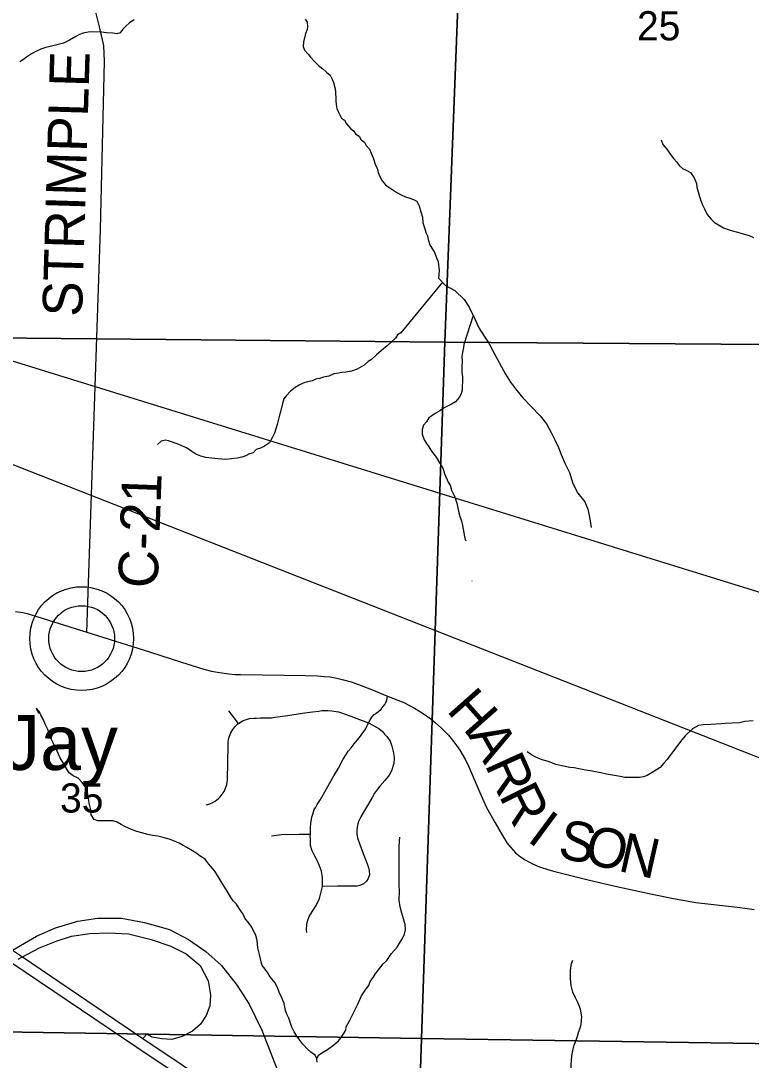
# Model space of a CAD drawing. Extents: x -7.5 to 26.5, y 3.5 to 25.5.
# Drawn here: x -0.916 to 0.131, y 19.097 to 20.587 of the extents above; entities that cross this region are included whole.
import ezdxf

# ---------------------------------------------------------------- set-up
doc = ezdxf.new("R2010")
doc.units = 0
for name, color, linetype in [('GM_X_Corporation', 7, 'Continuous'), ('GM_X_County_Road', 7, 'Continuous'), ('GM_X_County_Road_Text', 7, 'Continuous'), ('GM_X_Interchange_Ramps', 7, 'Continuous'), ('GM_X_Interstate_Route', 7, 'Continuous'), ('GM_X_Minor_River', 7, 'Continuous'), ('GM_X_Section_Text', 7, 'Continuous'), ('GM_X_Township_Road', 7, 'Continuous'), ('GM_X_Unincorporated', 7, 'Continuous'), ('GM_X_Unincorporated_Location', 7, 'Continuous'), ('GM_X_Unincorporated_Text', 7, 'Continuous'), ('GM_X_US_Route', 7, 'Continuous'), ('SH_Text', 7, 'Continuous')]:
    doc.layers.add(name, color=color, linetype=linetype)

msp = doc.modelspace()

# ---------------------------------------------------------------- linework, layer by layer
at = {"layer": 'GM_X_Corporation'}
for points in [[(-1.2798, 21.1309), (-1.0307, 21.1237), (-0.2705, 21.1018), (-0.3082, 20.1265), (-1.3089, 20.136)], [(-1.3089, 20.136), (-0.3082, 20.1265), (-0.3419, 19.1283), (-1.3364, 19.1437)], [(-0.3082, 20.1265), (0.6831, 20.1191), (0.6477, 19.1133), (-0.3419, 19.1283)], [(-0.3419, 19.1283), (-0.3746, 18.1372), (-1.2757, 18.1481), (-1.2769, 18.1576), (-1.2831, 18.1672), (-1.2995, 18.1782), (-1.3164, 18.1862), (-1.3281, 18.1892), (-1.3372, 18.1894), (-1.3579, 18.1948), (-1.3364, 19.1437)], [(0.6477, 19.1133), (0.6301, 18.1235), (-0.3746, 18.1372), (-0.3419, 19.1283)]]:
    msp.add_lwpolyline(points, close=True, dxfattribs=at)
msp.add_lwpolyline([(0.6831, 20.1191), (-0.3082, 20.1265), (-0.2705, 21.1018), (0.8624, 21.0618)], dxfattribs=at)
at = {"layer": 'GM_X_County_Road'}
for points in [[(-0.8217, 19.7108), (-0.8019, 20.2879), (-0.7964, 20.5294), (-0.7974, 20.5511), (-0.8024, 20.5748), (-0.8093, 20.6016), (-0.8189, 20.625), (-0.8374, 20.657), (-0.8664, 20.6927), (-0.8711, 20.6997), (-0.8729, 20.7047), (-0.872, 20.7107), (-0.7645, 20.9229), (-0.7533, 20.9424), (-0.7372, 20.9628), (-0.7249, 20.9811), (-0.717, 20.9931), (-0.7065, 21.016), (-0.689, 21.0677)], [(-0.9239, 19.7405), (-0.9133, 19.7386), (-0.9072, 19.7372), (-0.8936, 19.7333), (-0.8217, 19.7108), (-0.7318, 19.6823), (-0.686, 19.6678), (-0.6538, 19.6578), (-0.6427, 19.6549), (-0.6316, 19.6527), (-0.6182, 19.6508), (-0.6088, 19.6501), (-0.6011, 19.6498), (-0.5078, 19.6484), (-0.491, 19.6479), (-0.4814, 19.6472), (-0.4726, 19.6464), (-0.4633, 19.6448), (-0.4534, 19.6424), (-0.4427, 19.6392), (-0.432, 19.6354), (-0.4132, 19.6284), (-0.3902, 19.6189), (-0.3672, 19.6097), (-0.3515, 19.6015), (-0.3395, 19.5942), (-0.3284, 19.5863), (-0.3215, 19.5806), (-0.3136, 19.5736), (-0.3031, 19.563), (-0.2938, 19.5517), (-0.2865, 19.5413), (-0.2784, 19.5274), (-0.2736, 19.5175), (-0.2582, 19.481), (-0.2482, 19.4592), (-0.2358, 19.4373), (-0.2254, 19.4189), (-0.2227, 19.4143), (-0.2192, 19.4088), (-0.2137, 19.4019), (-0.2066, 19.3943), (-0.1996, 19.3886), (-0.193, 19.3841), (-0.1825, 19.3787), (-0.1725, 19.3743), (-0.1589, 19.3699), (-0.1503, 19.3674), (-0.1408, 19.3649), (-0.1007, 19.3551), (-0.0639, 19.3463), (-0.011, 19.335), (0.0198, 19.3289), (0.0518, 19.3232), (0.0986, 19.3179), (0.1151, 19.316), (0.1219, 19.3151)], [(0.1219, 19.3151), (0.1354, 19.3131)]]:
    msp.add_lwpolyline(points, dxfattribs=at)
at = {"layer": 'GM_X_Interchange_Ramps'}
msp.add_lwpolyline([(-0.9201, 19.2419), (-0.9141, 19.2451), (-0.8896, 19.2582), (-0.8659, 19.2678), (-0.8436, 19.2749), (-0.8172, 19.2788), (-0.7903, 19.2796), (-0.7618, 19.2779), (-0.7293, 19.2701), (-0.7013, 19.2604), (-0.6794, 19.2494), (-0.6593, 19.2328), (-0.6478, 19.2108), (-0.6443, 19.1909), (-0.6451, 19.1747), (-0.6507, 19.1609), (-0.6587, 19.1485), (-0.6699, 19.1387), (-0.685, 19.1307), (-0.6996, 19.1268), (-0.714, 19.1275), (-0.7279, 19.1302), (-0.7356, 19.1343), (-0.7414, 19.1282)], dxfattribs=at)
at = {"layer": 'GM_X_Interstate_Route'}
for points in [[(-2.5166, 20.6214), (-2.2641, 20.4567), (-2.2429, 20.4419), (-2.2259, 20.4305), (-2.2012, 20.4099), (-2.1752, 20.3875), (-2.1502, 20.3617), (-2.125, 20.3321), (-2.1026, 20.3014), (-2.0717, 20.2574), (-1.9284, 20.0555), (-1.9051, 20.0252), (-1.8815, 19.9963), (-1.8534, 19.9664), (-1.8086, 19.9202), (-1.7663, 19.8824), (-1.6536, 19.7958), (-1.4759, 19.6616), (-1.1953, 19.4501), (-1.116, 19.3907), (-0.9284, 19.2549), (-0.9141, 19.2451), (-0.7414, 19.1282), (-0.5126, 18.9753)], [(-1.2037, 19.4375), (-1.1244, 19.3781), (-0.9429, 19.2465), (-0.9291, 19.2366), (-0.7498, 19.1155), (-0.546, 18.9794)], [(-1.2112, 19.0844), (-0.9544, 19.2399), (-0.9429, 19.2465), (-0.9284, 19.2549), (-0.8938, 19.2749), (-0.8665, 19.2868), (-0.8345, 19.2963), (-0.8066, 19.3004), (-0.7722, 19.3004), (-0.7389, 19.2945), (-0.7033, 19.2844), (-0.676, 19.2702), (-0.6511, 19.2529), (-0.6285, 19.2327), (-0.606, 19.2042), (-0.5887, 19.1775), (-0.5709, 19.1401), (-0.5442, 19.0724)]]:
    msp.add_lwpolyline(points, dxfattribs=at)
at = {"layer": 'GM_X_Minor_River'}
for points in [[(-0.7536, 20.5887), (-0.7606, 20.5844), (-0.7657, 20.5797), (-0.77, 20.5753), (-0.774, 20.5701), (-0.7786, 20.5683), (-0.7846, 20.5693), (-0.7937, 20.57), (-0.8001, 20.571), (-0.8157, 20.5715), (-0.8199, 20.5709), (-0.8268, 20.5692), (-0.8321, 20.5675), (-0.8376, 20.5647), (-0.8465, 20.5593), (-0.855, 20.555), (-0.8592, 20.554), (-0.8665, 20.552), (-0.8745, 20.5504), (-0.8806, 20.5491), (-0.8879, 20.5463), (-0.8941, 20.5434), (-0.9011, 20.5399), (-0.9081, 20.5352), (-0.9123, 20.5319), (-0.9178, 20.5283)], [(-0.5083, 20.5897), (-0.5058, 20.5851), (-0.5052, 20.5786), (-0.5058, 20.5745), (-0.5079, 20.5688), (-0.5092, 20.5643), (-0.5109, 20.5572), (-0.5112, 20.5503), (-0.5094, 20.5449), (-0.504, 20.5391), (-0.5011, 20.5348), (-0.4948, 20.5285), (-0.4893, 20.5233), (-0.4834, 20.5182), (-0.4779, 20.5134), (-0.4727, 20.5091), (-0.4699, 20.5037), (-0.4678, 20.4987), (-0.4661, 20.4914), (-0.4652, 20.4864), (-0.4649, 20.4818), (-0.4647, 20.4776), (-0.4645, 20.4723), (-0.4639, 20.467), (-0.463, 20.4612), (-0.4612, 20.457), (-0.4562, 20.4477), (-0.4522, 20.4445), (-0.4493, 20.4395), (-0.4431, 20.4324), (-0.439, 20.4296), (-0.4358, 20.4246), (-0.4313, 20.4218), (-0.4281, 20.4163), (-0.4236, 20.4131), (-0.4208, 20.4085), (-0.4164, 20.403), (-0.4139, 20.3976), (-0.4111, 20.3907), (-0.4077, 20.3803), (-0.4052, 20.376), (-0.4039, 20.3695), (-0.4014, 20.3641), (-0.3982, 20.3579), (-0.3931, 20.352), (-0.3879, 20.348), (-0.3827, 20.3448), (-0.3772, 20.3412), (-0.3708, 20.3376), (-0.3645, 20.3347), (-0.36, 20.3334), (-0.3532, 20.3309), (-0.3484, 20.3284), (-0.3452, 20.3219), (-0.3424, 20.3134), (-0.3404, 20.3057), (-0.3396, 20.2977), (-0.3382, 20.2931), (-0.3368, 20.2889), (-0.3355, 20.2835), (-0.333, 20.2789), (-0.332, 20.2735), (-0.3296, 20.2662)], [(0.0021, 20.4166), (0.0045, 20.4097), (0.01, 20.4031), (0.0147, 20.3968), (0.0197, 20.3898), (0.0245, 20.3847), (0.0281, 20.3796), (0.0329, 20.3753), (0.0381, 20.3728), (0.0441, 20.3696), (0.0495, 20.3622), (0.0527, 20.3537), (0.0533, 20.3487), (0.0559, 20.3388), (0.0583, 20.3307), (0.0615, 20.3234), (0.0643, 20.3176), (0.0682, 20.3094), (0.0737, 20.3028), (0.0785, 20.2981), (0.0844, 20.2944), (0.0915, 20.2904), (0.0994, 20.2875), (0.1046, 20.2861), (0.1114, 20.284), (0.1182, 20.2823), (0.123, 20.2809), (0.1283, 20.2792), (0.1343, 20.2764)], [(-0.3296, 20.2662), (-0.3229, 20.2551), (-0.3176, 20.2416), (-0.3164, 20.229), (-0.3171, 20.218), (-0.3072, 20.2075), (-0.2937, 20.2006), (-0.2804, 20.1877), (-0.2731, 20.1765), (-0.2663, 20.1618), (-0.2596, 20.1468), (-0.2519, 20.1352), (-0.245, 20.1251), (-0.24, 20.1151), (-0.2331, 20.1027), (-0.227, 20.0912), (-0.2212, 20.0807), (-0.2139, 20.0691), (-0.207, 20.0594), (-0.1964, 20.0466), (-0.1713, 20.0208), (-0.1625, 20.0091), (-0.1557, 19.9967), (-0.1503, 19.9863), (-0.1453, 19.9755), (-0.1414, 19.9655), (-0.136, 19.9528), (-0.1296, 19.9397), (-0.1247, 19.9236), (-0.1175, 19.9101), (-0.1076, 19.8977), (-0.103, 19.8869), (-0.1004, 19.8731), (-0.0984, 19.8605)], [(-0.3117, 20.2122), (-0.3712, 20.1396), (-0.3763, 20.1367)], [(-0.2676, 20.1647), (-0.2811, 20.1232), (-0.2816, 20.1186), (-0.283, 20.1118), (-0.2836, 20.1058), (-0.2834, 20.0989), (-0.2837, 20.0917), (-0.2836, 20.0833), (-0.283, 20.0769), (-0.2829, 20.0708), (-0.2832, 20.0624), (-0.2833, 20.0575), (-0.2846, 20.0522), (-0.2875, 20.047), (-0.293, 20.0411), (-0.2984, 20.0375), (-0.3035, 20.035), (-0.3093, 20.0322), (-0.3155, 20.0282), (-0.3221, 20.0242), (-0.3267, 20.0206), (-0.331, 20.0177), (-0.3346, 20.0121), (-0.3386, 20.0073), (-0.3407, 20.0013), (-0.3406, 19.9945), (-0.3378, 19.9864), (-0.3346, 19.981), (-0.3313, 19.9763), (-0.3274, 19.9701), (-0.3208, 19.9615), (-0.3158, 19.9533), (-0.3111, 19.9456), (-0.308, 19.9367), (-0.3035, 19.9255), (-0.3006, 19.9213), (-0.2985, 19.9144), (-0.2943, 19.9058), (-0.2922, 19.9001), (-0.2908, 19.8958), (-0.2902, 19.8909), (-0.2879, 19.8817), (-0.2866, 19.8763), (-0.2845, 19.8702), (-0.2828, 19.8636), (-0.2819, 19.8583), (-0.2799, 19.848), (-0.2789, 19.8437), (-0.2782, 19.8415)], [(-0.3763, 20.1367), (-0.3791, 20.1323), (-0.3908, 20.1213), (-0.3991, 20.1143), (-0.4061, 20.1081), (-0.4135, 20.1015), (-0.4182, 20.0986), (-0.4241, 20.0935), (-0.4341, 20.0878), (-0.4422, 20.085), (-0.4502, 20.0834), (-0.456, 20.0828), (-0.4602, 20.0819), (-0.4674, 20.081), (-0.4747, 20.0778), (-0.4824, 20.0762), (-0.4878, 20.0741), (-0.4931, 20.0735), (-0.4981, 20.071), (-0.505, 20.0697), (-0.5115, 20.0677), (-0.5173, 20.0648), (-0.5231, 20.0616), (-0.5294, 20.0561), (-0.5357, 20.0495), (-0.5389, 20.0454), (-0.541, 20.0383), (-0.5437, 20.0266), (-0.5454, 20.0217), (-0.5467, 20.0161), (-0.5489, 20.0085), (-0.5506, 20.0021), (-0.5527, 19.9958), (-0.5552, 19.9901), (-0.5576, 19.986), (-0.5597, 19.9819), (-0.5667, 19.9772), (-0.5725, 19.9744), (-0.5786, 19.9723), (-0.5833, 19.9679), (-0.5895, 19.9659), (-0.5937, 19.9633), (-0.5995, 19.9616), (-0.606, 19.96), (-0.614, 19.9591), (-0.6231, 19.9583), (-0.6281, 19.9585), (-0.6334, 19.959), (-0.6379, 19.9596), (-0.6466, 19.9606), (-0.6508, 19.9611), (-0.6583, 19.9629), (-0.6654, 19.9658), (-0.671, 19.9698), (-0.6788, 19.9747), (-0.6896, 19.9796), (-0.699, 19.983), (-0.7046, 19.985), (-0.7087, 19.986), (-0.7149, 19.9846), (-0.7203, 19.9796)], [(-0.2689, 19.7837), (-0.269, 19.7842)], [(-0.4943, 19.1044), (-0.5003, 19.1084), (-0.5054, 19.1128), (-0.5117, 19.1198), (-0.5164, 19.1257), (-0.5211, 19.1323), (-0.5243, 19.1378), (-0.5275, 19.1443), (-0.5299, 19.1513), (-0.532, 19.157), (-0.5348, 19.1628), (-0.5366, 19.1682), (-0.5385, 19.1782), (-0.5417, 19.1855), (-0.5459, 19.1944), (-0.5476, 19.1997), (-0.5515, 19.2079), (-0.5588, 19.2165), (-0.562, 19.2223), (-0.566, 19.2274), (-0.57, 19.2328), (-0.5717, 19.2382), (-0.574, 19.2485), (-0.5763, 19.2581), (-0.5775, 19.2688), (-0.5795, 19.2757), (-0.5848, 19.2877), (-0.5888, 19.2931), (-0.595, 19.3006), (-0.5975, 19.3064), (-0.6033, 19.3145), (-0.6068, 19.3208), (-0.6116, 19.3255), (-0.6156, 19.3313), (-0.6206, 19.3395), (-0.626, 19.3484), (-0.6317, 19.3581), (-0.6379, 19.3678), (-0.6437, 19.3749), (-0.6488, 19.3804), (-0.6521, 19.3854), (-0.6591, 19.3895), (-0.6639, 19.3934), (-0.6703, 19.3971), (-0.6781, 19.4019), (-0.6837, 19.4047), (-0.6892, 19.408), (-0.6982, 19.4121), (-0.7038, 19.4138), (-0.7121, 19.4164), (-0.72, 19.4182), (-0.7276, 19.4192), (-0.7344, 19.4206), (-0.743, 19.4228), (-0.7498, 19.4249), (-0.755, 19.4266), (-0.7618, 19.4295), (-0.7674, 19.432), (-0.7726, 19.4348), (-0.7782, 19.438), (-0.7838, 19.4401), (-0.7895, 19.4403), (-0.7944, 19.4401), (-0.7994, 19.4403), (-0.8058, 19.4401), (-0.8114, 19.4422), (-0.8154, 19.4488), (-0.8166, 19.4576), (-0.8182, 19.4653), (-0.8191, 19.4733), (-0.821, 19.4832), (-0.8246, 19.4898), (-0.8286, 19.4949), (-0.8341, 19.5012), (-0.8412, 19.5045), (-0.8471, 19.5088), (-0.8503, 19.5143), (-0.8557, 19.5232), (-0.86, 19.5306), (-0.8621, 19.5356), (-0.8646, 19.541), (-0.8696, 19.551), (-0.8731, 19.5588), (-0.8755, 19.5657), (-0.8783, 19.5719), (-0.8808, 19.578), (-0.8843, 19.5861), (-0.8879, 19.5916), (-0.8896, 19.5966), (-0.8944, 19.6017), (-0.8912, 19.5947)], [(0.1342, 19.5835), (0.1221, 19.5825), (0.1144, 19.5808), (0.1037, 19.58), (0.0939, 19.5796), (0.0885, 19.5794), (0.0733, 19.5781), (0.0627, 19.5777), (0.0558, 19.5768), (0.0469, 19.5721), (0.0367, 19.5618), (0.03, 19.5541), (0.0232, 19.5448), (0.0156, 19.5348), (0.0105, 19.5282), (0.0057, 19.523), (0.0009, 19.5167), (-0.0045, 19.5131), (-0.0107, 19.5095), (-0.0181, 19.5052), (-0.0234, 19.5031), (-0.0288, 19.5022), (-0.039, 19.5021), (-0.05, 19.5025), (-0.0565, 19.5035), (-0.0648, 19.5049), (-0.0704, 19.5059), (-0.0761, 19.5072), (-0.0844, 19.509), (-0.0923, 19.5104), (-0.0995, 19.5118), (-0.1066, 19.5128), (-0.1138, 19.5142), (-0.1225, 19.516), (-0.1289, 19.5167), (-0.1357, 19.518), (-0.1406, 19.519), (-0.1489, 19.5211), (-0.1549, 19.5232), (-0.1616, 19.5258), (-0.1688, 19.5275), (-0.1785, 19.532), (-0.1837, 19.5349), (-0.19, 19.5389)], [(-0.492, 19.0993), (-0.489, 19.1046), (-0.4824, 19.1089), (-0.4766, 19.1122), (-0.4676, 19.1191), (-0.4606, 19.1249), (-0.4562, 19.1301), (-0.4534, 19.1349), (-0.4502, 19.1401), (-0.4497, 19.145), (-0.4448, 19.1532), (-0.4411, 19.1611), (-0.4383, 19.1667), (-0.4334, 19.1764), (-0.4276, 19.1891), (-0.4212, 19.1992), (-0.4172, 19.204), (-0.4152, 19.2096), (-0.4111, 19.2155), (-0.4079, 19.2204), (-0.4032, 19.2263), (-0.3968, 19.2352), (-0.3913, 19.2399), (-0.3849, 19.25), (-0.3766, 19.2592), (-0.3722, 19.2663), (-0.3682, 19.2722), (-0.3661, 19.2778), (-0.3647, 19.2839), (-0.3652, 19.2915), (-0.3666, 19.2965), (-0.3683, 19.303), (-0.37, 19.308), (-0.3723, 19.3168), (-0.3735, 19.3264), (-0.3731, 19.34), (-0.3736, 19.3476), (-0.3736, 19.3583), (-0.3737, 19.3666), (-0.3738, 19.3735), (-0.3739, 19.3826), (-0.3736, 19.391), (-0.3738, 19.3967), (-0.3735, 19.4035), (-0.3733, 19.4107), (-0.3726, 19.4167)], [(-0.1257, 19.0715), (-0.1269, 19.0811), (-0.1269, 19.0906), (-0.1267, 19.0962), (-0.1261, 19.1031), (-0.1243, 19.1129), (-0.1225, 19.1185), (-0.1196, 19.1256), (-0.1179, 19.1313), (-0.1166, 19.1366), (-0.1141, 19.1433), (-0.1128, 19.1482), (-0.1122, 19.1543), (-0.1116, 19.1592), (-0.1126, 19.1649), (-0.1135, 19.1703), (-0.117, 19.1788), (-0.121, 19.1865), (-0.1245, 19.1946), (-0.1268, 19.2042), (-0.128, 19.2141), (-0.128, 19.2255), (-0.1265, 19.2357), (-0.1248, 19.2406)], [(-0.4913, 19.094), (-0.4919, 19.099), (-0.4943, 19.1044)]]:
    msp.add_lwpolyline(points, dxfattribs=at)
at = {"layer": 'GM_X_Township_Road'}
msp.add_line((-0.6041, 19.5797), (-0.6178, 19.5977), dxfattribs=at)
for points in [[(-0.5063, 19.2802), (-0.5065, 19.2841), (-0.5063, 19.2916), (-0.5051, 19.2965), (-0.5029, 19.3032), (-0.4981, 19.3108), (-0.4928, 19.3189), (-0.4878, 19.3286), (-0.4855, 19.3384), (-0.4839, 19.3458), (-0.4838, 19.3586), (-0.4853, 19.3682), (-0.4879, 19.3755), (-0.4913, 19.3835), (-0.4961, 19.3924), (-0.4984, 19.3972), (-0.5007, 19.4049), (-0.5011, 19.4142), (-0.5012, 19.4174), (-0.5009, 19.421), (-0.5008, 19.4302), (-0.5005, 19.4367), (-0.4996, 19.4419), (-0.4989, 19.4455), (-0.4976, 19.4498), (-0.4967, 19.4531), (-0.4954, 19.4566), (-0.4932, 19.4598), (-0.4912, 19.4635), (-0.4865, 19.4707), (-0.4675, 19.5045), (-0.4607, 19.5156), (-0.4539, 19.5286), (-0.4497, 19.5354), (-0.4468, 19.5398), (-0.4427, 19.5449), (-0.4382, 19.5507), (-0.4334, 19.5563), (-0.4291, 19.5617), (-0.4261, 19.5658), (-0.423, 19.5703), (-0.4211, 19.5735), (-0.4196, 19.5767), (-0.4182, 19.5791), (-0.4178, 19.5807), (-0.416, 19.5842), (-0.4128, 19.5886), (-0.4097, 19.5926), (-0.4068, 19.5946), (-0.4034, 19.5968), (-0.3995, 19.6002), (-0.3966, 19.6041), (-0.3944, 19.6071), (-0.3929, 19.6096), (-0.3919, 19.6123), (-0.3907, 19.6153), (-0.3902, 19.6189)], [(-0.6505, 19.4631), (-0.6454, 19.4647), (-0.6411, 19.4666), (-0.6377, 19.4684), (-0.6326, 19.472), (-0.6303, 19.4747), (-0.6274, 19.4782), (-0.6249, 19.4821), (-0.6226, 19.4872), (-0.6211, 19.4921), (-0.6205, 19.4956), (-0.6201, 19.4996), (-0.6192, 19.5487), (-0.6191, 19.5513), (-0.6185, 19.5571), (-0.6172, 19.5616), (-0.6153, 19.5663), (-0.6124, 19.5712), (-0.6094, 19.5749), (-0.605, 19.5791), (-0.6041, 19.5797), (-0.5974, 19.5838), (-0.5913, 19.586), (-0.5886, 19.5867), (-0.5816, 19.5873), (-0.5787, 19.5875), (-0.5726, 19.5877), (-0.5669, 19.5877), (-0.5618, 19.5877), (-0.5567, 19.588), (-0.554, 19.5883), (-0.5518, 19.5886), (-0.5446, 19.5896), (-0.5339, 19.5911), (-0.5187, 19.5934), (-0.5088, 19.5948), (-0.498, 19.5964), (-0.489, 19.5976), (-0.4845, 19.5982), (-0.4795, 19.5984), (-0.4762, 19.5984), (-0.4702, 19.598), (-0.464, 19.5971), (-0.4606, 19.5964), (-0.4565, 19.5951), (-0.451, 19.5933), (-0.443, 19.5901), (-0.4344, 19.5868), (-0.4178, 19.5807), (-0.4115, 19.5771), (-0.4031, 19.5726), (-0.3978, 19.5681), (-0.3945, 19.5646), (-0.3914, 19.5609), (-0.3867, 19.5543), (-0.3842, 19.5471), (-0.3818, 19.5378), (-0.3809, 19.5301), (-0.3814, 19.5222), (-0.3847, 19.5118), (-0.3882, 19.5056), (-0.3942, 19.4982), (-0.4012, 19.4899), (-0.4049, 19.4854), (-0.4089, 19.4797), (-0.4122, 19.4738), (-0.4176, 19.4647), (-0.4232, 19.4548), (-0.4285, 19.4457), (-0.4319, 19.439), (-0.433, 19.4357), (-0.4341, 19.4309), (-0.4345, 19.4266), (-0.4343, 19.4212), (-0.4335, 19.4159), (-0.4302, 19.4063), (-0.4267, 19.397), (-0.4222, 19.3849), (-0.4184, 19.3748), (-0.4165, 19.3685), (-0.4164, 19.3628), (-0.4181, 19.3574), (-0.4207, 19.3535), (-0.4247, 19.3498), (-0.4302, 19.3473), (-0.4339, 19.3467), (-0.4426, 19.3467), (-0.4621, 19.3465), (-0.4839, 19.3458)], [(-0.5567, 19.4188), (-0.5429, 19.4207), (-0.517, 19.421), (-0.5095, 19.4211), (-0.5009, 19.421)]]:
    msp.add_lwpolyline(points, dxfattribs=at)
at = {"layer": 'GM_X_Unincorporated'}
for radius in [0.0744, 0.0472]:
    msp.add_circle((-0.8291, 19.7014), radius, dxfattribs=at)
at = {"layer": 'GM_X_Unincorporated_Location'}
msp.add_line((-0.8291, 19.7014), (-0.8291, 19.7014), dxfattribs=at)
at = {"layer": 'GM_X_US_Route'}
msp.add_lwpolyline([(-1.2037, 19.4375), (-1.1244, 19.3781), (-0.9429, 19.2465), (-0.9291, 19.2366), (-0.7498, 19.1155), (-0.546, 18.9794)], dxfattribs=at)
at = {"layer": 'SH_Text'}
msp.add_lwpolyline([(2.5135, 19.0346), (-2.7067, 20.6498), (2.5135, 18.5999)], close=True, dxfattribs=at)

# ---------------------------------------------------------------- texts
at = {"layer": 'GM_X_County_Road_Text'}
for s, height, rotation, p in [('STRIMPLE', 0.05682, 88.3029, (-0.8287, 20.1623)), ('C-21', 0.05682, 87.9423, (-0.7202, 19.773)), ('H', 0.0568, 311.5766, (-0.307, 19.598)), ('A', 0.0568, 299.6497, (-0.2756, 19.5631)), ('R', 0.0568, 294.3059, (-0.2515, 19.5209)), ('R', 0.0568, 296.4658, (-0.2313, 19.4763)), ('I', 0.0568, 323.5697, (-0.1918, 19.4122)), ('S', 0.0568, 349.4089, (-0.1476, 19.3873)), ('O', 0.0568, 346.7014, (-0.1106, 19.3804)), ('N', 0.0568, 347.3367, (-0.0613, 19.3687))]:
    msp.add_text(s, height=height, rotation=rotation, dxfattribs=at).set_placement(p)
at = {"layer": 'GM_X_Section_Text'}
for s, p in [('25', (-0.0326, 20.5591)), ('35', (-0.8601, 19.452))]:
    msp.add_text(s, height=0.04186, rotation=0, dxfattribs=at).set_placement(p)
at = {"layer": 'GM_X_Unincorporated_Text'}
msp.add_text('Blue Jay', height=0.07898, rotation=0, dxfattribs=at).set_placement((-1.1822, 19.5131))

doc.saveas('drawing.dxf')
